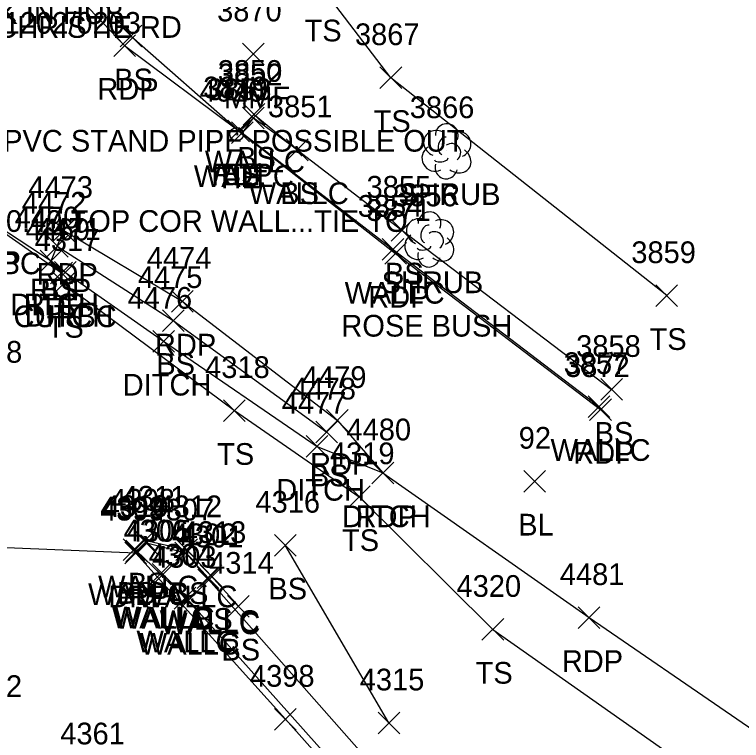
# Model space of a CAD drawing. Extents: x 1634209 to 1639641, y 608564 to 612258.
# Drawn here: x 1639319.3 to 1639386.3, y 611460.6 to 611527.5 of the extents above; entities that cross this region are included whole.
import ezdxf

# ---------------------------------------------------------------- set-up
doc = ezdxf.new("R2010")
doc.units = 0
for name, color, linetype in [('C_A', 7, 'Continuous'), ('C_C', 7, 'Continuous'), ('C_I', 7, 'Continuous'), ('C_TIC', 7, 'Continuous'), ('CBP', 7, 'Continuous'), ('D_A', 7, 'Continuous'), ('D_I', 7, 'Continuous'), ('D_TIC', 7, 'Continuous'), ('DD', 7, 'Continuous'), ('L_A', 7, 'Continuous'), ('L_C', 7, 'Continuous'), ('L_I', 7, 'Continuous'), ('L_TIC', 7, 'Continuous'), ('LELB', 7, 'Continuous'), ('LSH', 7, 'Continuous'), ('LW', 7, 'Continuous'), ('M_C', 7, 'Continuous'), ('P_A', 7, 'Continuous'), ('P_I', 7, 'Continuous'), ('P_TIC', 7, 'Continuous'), ('PET', 7, 'Continuous'), ('R_A', 7, 'Continuous'), ('R_I', 7, 'Continuous'), ('R_TIC', 7, 'Continuous'), ('RC', 7, 'Continuous'), ('RDP', 7, 'Continuous'), ('S_C', 7, 'Continuous')]:
    doc.layers.add(name, color=color, linetype=linetype)

msp = doc.modelspace()

# ---------------------------------------------------------------- linework, layer by layer
at = {"layer": 'C_TIC'}
for points in [[(1639366.207, 611483.502), (1639368.207, 611485.502)], [(1639368.207, 611483.502), (1639366.207, 611485.502)]]:
    msp.add_lwpolyline(points, dxfattribs=at)
at = {"layer": 'CBP'}
for radius in [0.625, 0.0833]:
    msp.add_circle((1639339.766, 611516.474), radius, dxfattribs=at)
at = {"layer": 'D_TIC'}
for points in [[(1639321.657, 611503.794), (1639323.657, 611505.794)], [(1639323.657, 611503.794), (1639321.657, 611505.794)], [(1639322.986, 611502.739), (1639324.986, 611504.739)], [(1639324.986, 611502.739), (1639322.986, 611504.739)], [(1639332.024, 611496.396), (1639334.024, 611498.396)], [(1639334.024, 611496.396), (1639332.024, 611498.396)], [(1639346.171, 611486.713), (1639348.171, 611488.713)], [(1639348.171, 611486.713), (1639346.171, 611488.713)], [(1639352.223, 611484.268), (1639354.223, 611486.268)], [(1639354.223, 611484.268), (1639352.223, 611486.268)]]:
    msp.add_lwpolyline(points, dxfattribs=at)
at = {"layer": 'DD'}
msp.add_lwpolyline([(1639322.657, 611504.794), (1639323.986, 611503.739), (1639333.024, 611497.396), (1639347.171, 611487.713), (1639353.223, 611485.268)], dxfattribs=at)
at = {"layer": 'L_TIC'}
for points in [[(1639329.033, 611524.513), (1639331.033, 611526.513)], [(1639331.033, 611524.513), (1639329.033, 611526.513)], [(1639340.304, 611522.866), (1639342.304, 611524.866)], [(1639342.304, 611522.866), (1639340.304, 611524.866)], [(1639352.963, 611520.678), (1639354.963, 611522.678)], [(1639354.963, 611520.678), (1639352.963, 611522.678)], [(1639340.362, 611517.296), (1639342.362, 611519.296)], [(1639342.362, 611517.296), (1639340.362, 611519.296)], [(1639340.292, 611516.968), (1639342.292, 611518.968)], [(1639342.292, 611516.968), (1639340.292, 611518.968)], [(1639338.944, 611515.771), (1639340.944, 611517.771)], [(1639340.944, 611515.771), (1639338.944, 611517.771)], [(1639339.276, 611515.609), (1639341.276, 611517.609)], [(1639341.276, 611515.609), (1639339.276, 611517.609)], [(1639344.333, 611514.034), (1639346.333, 611516.034)], [(1639346.333, 611514.034), (1639344.333, 611516.034)], [(1639344.333, 611514.034), (1639346.333, 611516.034)], [(1639346.333, 611514.034), (1639344.333, 611516.034)], [(1639353.985, 611506.628), (1639355.985, 611508.628)], [(1639355.985, 611506.628), (1639353.985, 611508.628)], [(1639322.225, 611505.158), (1639324.225, 611507.158)], [(1639324.225, 611505.158), (1639322.225, 611507.158)], [(1639353.17, 611504.865), (1639355.17, 611506.865)], [(1639355.17, 611504.865), (1639353.17, 611506.865)], [(1639322.847, 611501.725), (1639324.847, 611503.725)], [(1639324.847, 611501.725), (1639322.847, 611503.725)], [(1639378.384, 611500.598), (1639380.384, 611502.598)], [(1639380.384, 611500.598), (1639378.384, 611502.598)], [(1639332.914, 611498.304), (1639334.914, 611500.304)], [(1639334.914, 611498.304), (1639332.914, 611500.304)], [(1639373.294, 611491.958), (1639375.294, 611493.958)], [(1639375.294, 611491.958), (1639373.294, 611493.958)], [(1639372.143, 611490.379), (1639374.143, 611492.379)], [(1639374.143, 611490.379), (1639372.143, 611492.379)], [(1639338.548, 611490.013), (1639340.548, 611492.013)], [(1639340.548, 611490.013), (1639338.548, 611492.013)], [(1639347.053, 611488.031), (1639349.053, 611490.031)], [(1639349.053, 611488.031), (1639347.053, 611490.031)], [(1639350.056, 611482.073), (1639352.056, 611484.073)], [(1639352.056, 611482.073), (1639350.056, 611484.073)], [(1639330.299, 611478.069), (1639332.299, 611480.069)], [(1639332.299, 611478.069), (1639330.299, 611480.069)], [(1639330.455, 611477.798), (1639332.455, 611479.798)], [(1639332.455, 611477.798), (1639330.455, 611479.798)], [(1639343.241, 611477.608), (1639345.241, 611479.608)], [(1639345.241, 611477.608), (1639343.241, 611479.608)], [(1639329.289, 611477.208), (1639331.289, 611479.208)], [(1639331.289, 611477.208), (1639329.289, 611479.208)], [(1639329.539, 611477.086), (1639331.539, 611479.086)], [(1639331.539, 611477.086), (1639329.539, 611479.086)], [(1639329.539, 611477.086), (1639331.539, 611479.086)], [(1639331.539, 611477.086), (1639329.539, 611479.086)], [(1639334.156, 611477.192), (1639336.156, 611479.192)], [(1639336.156, 611477.192), (1639334.156, 611479.192)], [(1639334.074, 611476.887), (1639336.074, 611478.887)], [(1639336.074, 611476.887), (1639334.074, 611478.887)], [(1639331.73, 611474.958), (1639333.73, 611476.958)], [(1639333.73, 611474.958), (1639331.73, 611476.958)], [(1639331.968, 611474.929), (1639333.968, 611476.929)], [(1639333.968, 611474.929), (1639331.968, 611476.929)], [(1639336.126, 611474.615), (1639338.126, 611476.615)], [(1639338.126, 611474.615), (1639336.126, 611476.615)], [(1639336.188, 611474.408), (1639338.188, 611476.408)], [(1639338.188, 611474.408), (1639336.188, 611476.408)], [(1639336.387, 611474.815), (1639338.387, 611476.815)], [(1639338.387, 611474.815), (1639336.387, 611476.815)], [(1639333.995, 611472.73), (1639335.995, 611474.73)], [(1639335.995, 611472.73), (1639333.995, 611474.73)], [(1639334.302, 611472.537), (1639336.302, 611474.537)], [(1639336.302, 611472.537), (1639334.302, 611474.537)], [(1639338.915, 611471.986), (1639340.915, 611473.986)], [(1639340.915, 611471.986), (1639338.915, 611473.986)], [(1639362.36, 611469.852), (1639364.36, 611471.852)], [(1639364.36, 611469.852), (1639362.36, 611471.852)], [(1639352.791, 611461.233), (1639354.791, 611463.233)], [(1639354.791, 611461.233), (1639352.791, 611463.233)]]:
    msp.add_lwpolyline(points, dxfattribs=at)
at = {"layer": 'LELB'}
for points in [[(1639319.732, 611545.773), (1639322.72, 611534.263), (1639330.033, 611525.513), (1639339.944, 611516.771), (1639341.362, 611518.296), (1639345.333, 611515.034), (1639354.985, 611507.628), (1639374.294, 611492.958)], [(1639379.384, 611501.598), (1639353.963, 611521.678), (1639347.601, 611530.023), (1639334.248, 611539.828)], [(1639323.225, 611506.158), (1639333.914, 611499.304), (1639348.053, 611489.031)], [(1639323.847, 611502.725), (1639339.548, 611491.013), (1639351.056, 611483.073), (1639363.36, 611470.852), (1639390.679, 611451.611), (1639402.909, 611427.46), (1639391.145, 611410.38), (1639370.449, 611391.907), (1639349.836, 611374.39), (1639349.875, 611367.832), (1639363.625, 611352.92)], [(1639330.289, 611478.208), (1639331.299, 611479.069), (1639335.156, 611478.192), (1639337.387, 611475.815), (1639339.915, 611472.986)], [(1639353.791, 611462.233), (1639344.241, 611478.608)]]:
    msp.add_lwpolyline(points, dxfattribs=at)
at = {"layer": 'LSH'}
for p, q in [((1639359.069, 611514.952), (1639359.069, 611514.952)), ((1639359.069, 611514.952), (1639359.069, 611514.952)), ((1639357.483, 611506.828), (1639357.483, 611506.828)), ((1639357.483, 611506.828), (1639357.483, 611506.828))]:
    msp.add_line(p, q, dxfattribs=at)
for centre in [(1639359.116, 611516.385), (1639357.529, 611508.262)]:
    msp.add_arc(centre, 1.047, 335.52715, 180.95627, dxfattribs=at)
for centre, major_axis, ratio, start_param, end_param in [((1639358.278, 611515.618), (1.21, -0.512), 0.895232, 1.570796, 4.712389), ((1639360.111, 611515.535), (-1.141, -0.483), 0.949671, 1.570796, 4.712389), ((1639358.861, 611515.41), (-0.208, -0.792), 0.645439, 3.141593, 6.283185), ((1639357.986, 611514.243), (0.584, -1.042), 0.959034, 3.141593, 6.283185), ((1639359.569, 611514.785), (-0.5, 0.667), 0.989748, 3.141593, 6.283185), ((1639360.07, 611514.118), (-1.09, 0.792), 0.841452, 1.570796, 4.712389), ((1639358.611, 611514.201), (-0.625, -0.083), 0.423636, 0, 3.141593), ((1639359.07, 611513.452), (0.265, 1.061), 0.942809, 1.570796, 4.712389), ((1639356.691, 611507.495), (1.21, -0.512), 0.895232, 1.570796, 4.712389), ((1639358.524, 611507.412), (-1.141, -0.483), 0.949671, 1.570796, 4.712389), ((1639357.274, 611507.287), (-0.208, -0.792), 0.645439, 3.141593, 6.283185), ((1639356.399, 611506.12), (0.584, -1.042), 0.959034, 3.141593, 6.283185), ((1639357.983, 611506.662), (-0.5, 0.667), 0.989748, 3.141593, 6.283185), ((1639358.483, 611505.995), (-1.09, 0.792), 0.841452, 1.570796, 4.712389), ((1639357.024, 611506.078), (-0.625, -0.083), 0.423636, 0, 3.141593), ((1639357.483, 611505.328), (0.265, 1.061), 0.942809, 1.570796, 4.712389)]:
    msp.add_ellipse(centre, major_axis=major_axis, ratio=ratio, start_param=start_param, end_param=end_param, dxfattribs=at)
at = {"layer": 'LW'}
for points in [[(1639345.333, 611515.034), (1639341.292, 611517.968), (1639340.276, 611516.609), (1639354.17, 611505.865), (1639373.143, 611491.379)], [(1639350.672, 611344.201), (1639330.699, 611370.33), (1639326.662, 611374.868), (1639351.89, 611402.586), (1639353.191, 611402.191), (1639371.825, 611423.866), (1639369.52, 611438.787), (1639337.188, 611475.408), (1639337.126, 611475.615), (1639335.074, 611477.887), (1639331.455, 611478.798), (1639330.539, 611478.086)], [(1639347.959, 611343.04), (1639328.333, 611368.981), (1639322.617, 611374.773), (1639350.079, 611404.446), (1639350.847, 611404.494), (1639369.725, 611425.901), (1639367.306, 611437.612), (1639335.302, 611473.537), (1639334.995, 611473.73), (1639332.968, 611475.929), (1639332.73, 611475.958), (1639330.539, 611478.086)]]:
    msp.add_lwpolyline(points, dxfattribs=at)
at = {"layer": 'P_TIC'}
for points in [[(1639328.438, 611523.641), (1639330.438, 611525.641)], [(1639330.438, 611523.641), (1639328.438, 611525.641)], [(1639338.944, 611515.771), (1639340.944, 611517.771)], [(1639340.944, 611515.771), (1639338.944, 611517.771)], [(1639322.83, 611506.6), (1639324.83, 611508.6)], [(1639324.83, 611506.6), (1639322.83, 611508.6)], [(1639322.225, 611505.158), (1639324.225, 611507.158)], [(1639324.225, 611505.158), (1639322.225, 611507.158)], [(1639353.394, 611504.486), (1639355.394, 611506.486)], [(1639355.394, 611504.486), (1639353.394, 611506.486)], [(1639321.657, 611503.794), (1639323.657, 611505.794)], [(1639323.657, 611503.794), (1639321.657, 611505.794)], [(1639333.74, 611500.085), (1639335.74, 611502.085)], [(1639335.74, 611500.085), (1639333.74, 611502.085)], [(1639372.276, 611490.106), (1639374.276, 611492.106)], [(1639374.276, 611490.106), (1639372.276, 611492.106)], [(1639348.037, 611489.097), (1639350.037, 611491.097)], [(1639350.037, 611489.097), (1639348.037, 611491.097)], [(1639352.223, 611484.268), (1639354.223, 611486.268)], [(1639354.223, 611484.268), (1639352.223, 611486.268)], [(1639371.223, 611470.939), (1639373.223, 611472.939)], [(1639373.223, 611470.939), (1639371.223, 611472.939)]]:
    msp.add_lwpolyline(points, dxfattribs=at)
at = {"layer": 'PET'}
for points in [[(1639314.656, 611547.033), (1639316.63, 611540.173), (1639320.993, 611533.529), (1639329.438, 611524.641), (1639339.944, 611516.771), (1639354.394, 611505.486), (1639373.276, 611491.106)], [(1639267.876, 611454.496), (1639285.596, 611485.313), (1639298.768, 611508.597), (1639301.735, 611510.388), (1639304.907, 611511.217), (1639309.937, 611511.307), (1639314.005, 611510.179), (1639316.743, 611508.691), (1639322.657, 611504.794), (1639323.225, 611506.158), (1639323.83, 611507.6), (1639334.74, 611501.085), (1639349.037, 611490.097), (1639353.223, 611485.268), (1639372.223, 611471.939), (1639399.454, 611453.276)]]:
    msp.add_lwpolyline(points, dxfattribs=at)
at = {"layer": 'R_TIC'}
for points in [[(1639322.62, 611502.693), (1639324.62, 611504.693)], [(1639324.62, 611502.693), (1639322.62, 611504.693)], [(1639329.454, 611476.882), (1639331.454, 611478.882)], [(1639331.454, 611476.882), (1639329.454, 611478.882)], [(1639343.247, 611461.57), (1639345.247, 611463.57)], [(1639345.247, 611461.57), (1639343.247, 611463.57)]]:
    msp.add_lwpolyline(points, dxfattribs=at)
at = {"layer": 'RC'}
msp.add_lwpolyline([(1639305.25, 611502.148), (1639304.277, 611500.747), (1639292.233, 611481.833), (1639291.134, 611480.575), (1639289.383, 611479.947), (1639287.929, 611480.279), (1639286.687, 611481.225), (1639285.788, 611482.527), (1639285.487, 611483.753), (1639285.827, 611485.239), (1639298.852, 611508.417), (1639301.855, 611510.301), (1639304.868, 611511.156), (1639309.979, 611511.225), (1639313.824, 611510.093), (1639316.634, 611508.571), (1639323.62, 611503.693)], dxfattribs=at)
at = {"layer": 'RDP'}
msp.add_lwpolyline([(1639344.001, 611398.538), (1639368.892, 611426.032), (1639366.487, 611437.613), (1639344.247, 611462.57), (1639330.454, 611477.882), (1639311.81, 611478.629), (1639290.862, 611480.062), (1639289.304, 611479.764), (1639287.86, 611480.101), (1639286.517, 611481.064), (1639285.661, 611482.423), (1639285.361, 611483.798), (1639285.596, 611485.313)], dxfattribs=at)

# ---------------------------------------------------------------- texts
at = {"layer": 'C_A'}
for s, p in [('TIE', (1639337.845, 611511.474)), ('BL', (1639365.695, 611479.502))]:
    msp.add_text(s, height=2, dxfattribs=at).set_placement(p)
at = {"layer": 'C_C'}
for s, p in [('TACK IN HUB', (1639312.458, 611526.62)), ('70.49 TOP COR WALL...TIE TO', (1639317.018, 611507.474))]:
    msp.add_text(s, height=2, dxfattribs=at).set_placement(p)
at = {"layer": 'C_I'}
for s, p in [('4020', (1639336.341, 611519.474)), ('92', (1639365.742, 611487.502))]:
    msp.add_text(s, height=2, dxfattribs=at).set_placement(p)
at = {"layer": 'D_A'}
for p in [(1639318.893, 611499.794), (1639320.222, 611498.739), (1639329.26, 611492.396), (1639343.407, 611482.713), (1639349.459, 611480.268)]:
    msp.add_text('DITCH', height=2, dxfattribs=at).set_placement(p)
at = {"layer": 'D_I'}
for s, p in [('4470', (1639319.31, 611507.794)), ('4471', (1639321.293, 611506.739)), ('4476', (1639329.709, 611500.396)), ('4477', (1639343.911, 611490.713)), ('4480', (1639349.876, 611488.268))]:
    msp.add_text(s, height=2, dxfattribs=at).set_placement(p)
at = {"layer": 'L_A'}
for s, p in [('TS', (1639346.01, 611525.023)), ('BS', (1639328.474, 611520.513)), ('MMF', (1639338.588, 611518.866)), ('TS', (1639352.373, 611516.678)), ('BS', (1639339.803, 611513.296)), ('WALLC', (1639336.828, 611512.968)), ('BS', (1639338.385, 611511.771)), ('WALLC', (1639335.812, 611511.609)), ('WALLC', (1639340.869, 611510.034)), ('BS', (1639343.774, 611510.034)), ('SHRUB', (1639354.699, 611509.952)), ('BS', (1639353.426, 611502.628)), ('SHRUB', (1639353.113, 611501.828)), ('BS', (1639321.666, 611501.158)), ('WALLC', (1639349.706, 611500.865)), ('TS', (1639322.256, 611497.725)), ('TS', (1639377.793, 611496.598)), ('BS', (1639332.355, 611494.304)), ('BS', (1639372.735, 611487.958)), ('WALLC', (1639368.678, 611486.379)), ('TS', (1639337.957, 611486.013)), ('BS', (1639346.494, 611484.031)), ('TS', (1639349.465, 611478.073)), ('WALLC', (1639326.991, 611473.798)), ('BS', (1639329.74, 611474.069)), ('BS', (1639342.682, 611473.608)), ('WALLC', (1639326.075, 611473.086)), ('WALLC', (1639326.075, 611473.086)), ('BS', (1639328.73, 611473.208)), ('WALLC', (1639330.61, 611472.887)), ('BS', (1639333.597, 611473.192)), ('WALLC', (1639328.265, 611470.958)), ('WALLC', (1639328.504, 611470.929)), ('WALLC', (1639332.662, 611470.615)), ('WALLC', (1639332.724, 611470.408)), ('BS', (1639335.828, 611470.815)), ('WALLC', (1639330.53, 611468.73)), ('WALLC', (1639330.837, 611468.537)), ('BS', (1639338.356, 611467.986)), ('TS', (1639361.769, 611465.852))]:
    msp.add_text(s, height=2, dxfattribs=at).set_placement(p)
at = {"layer": 'L_C'}
for s, p in [('50 PVC STAND PIPE POSSIBLE OUT', (1639314.525, 611514.866)), ('ROSE BUSH', (1639349.404, 611497.828))]:
    msp.add_text(s, height=2, dxfattribs=at).set_placement(p)
at = {"layer": 'L_I'}
for s, p in [('3870', (1639337.958, 611526.866)), ('3867', (1639350.656, 611524.678)), ('3850', (1639338.015, 611521.296)), ('3852', (1639338.032, 611520.968)), ('3849', (1639336.677, 611519.771)), ('3853', (1639337.017, 611519.609)), ('3851', (1639342.64, 611518.034)), ('3851', (1639342.64, 611518.034)), ('3866', (1639355.707, 611517.952)), ('3855', (1639351.725, 611510.628)), ('3856', (1639354.168, 611509.828)), ('4472', (1639319.965, 611509.158)), ('3854', (1639350.91, 611508.865)), ('4317', (1639321.154, 611505.725)), ('3859', (1639376.116, 611504.598)), ('4475', (1639330.654, 611502.304)), ('3858', (1639371.034, 611495.958)), ('3857', (1639369.883, 611494.379)), ('4318', (1639336.855, 611494.013)), ('4478', (1639344.794, 611492.031)), ('4319', (1639348.355, 611486.073)), ('4308', (1639328.117, 611481.798)), ('4311', (1639329.173, 611482.069)), ('4316', (1639341.493, 611481.608)), ('4309', (1639327.193, 611481.086)), ('4309', (1639327.193, 611481.086)), ('4310', (1639327.51, 611481.208)), ('4312', (1639332.463, 611481.192)), ('4307', (1639331.736, 611480.887)), ('4306', (1639329.336, 611478.958)), ('4305', (1639329.63, 611478.929)), ('4302', (1639333.788, 611478.615)), ('4301', (1639334.417, 611478.408)), ('4313', (1639334.694, 611478.815)), ('4304', (1639331.656, 611476.73)), ('4303', (1639331.963, 611476.537)), ('4314', (1639337.223, 611475.986)), ('4320', (1639360.013, 611473.852)), ('4315', (1639351.098, 611465.233)), ('4362', (1639314.04, 611464.628)), ('4361', (1639323.508, 611460.263))]:
    msp.add_text(s, height=2, dxfattribs=at).set_placement(p)
at = {"layer": 'M_C'}
msp.add_text('WITH CAP D + A R BELL LS638', height=2, dxfattribs=at).set_placement((1639280.988, 611495.423))
at = {"layer": 'P_A'}
for p in [(1639326.926, 611519.641), (1639337.432, 611511.771), (1639314.231, 611503.691), (1639321.318, 611502.6), (1639320.713, 611501.158), (1639351.882, 611500.486), (1639320.145, 611499.794), (1639332.229, 611496.085), (1639370.764, 611486.106), (1639346.525, 611485.097), (1639350.711, 611480.268), (1639369.711, 611466.939)]:
    msp.add_text('RDP', height=2, dxfattribs=at).set_placement(p)
at = {"layer": 'P_I'}
for s, p in [('3849', (1639336.677, 611519.771)), ('4473', (1639320.57, 611510.6)), ('4472', (1639319.965, 611509.158)), ('3871', (1639351.701, 611508.486)), ('4470', (1639319.31, 611507.794)), ('4474', (1639331.481, 611504.085)), ('3872', (1639370.017, 611494.106)), ('4479', (1639345.769, 611493.097)), ('4480', (1639349.876, 611488.268)), ('4481', (1639369.53, 611474.939))]:
    msp.add_text(s, height=2, dxfattribs=at).set_placement(p)
at = {"layer": 'R_A'}
for s, p in [('CURBC', (1639312.217, 611503.571)), ('CURBC', (1639319.203, 611498.693)), ('DRP', (1639327.942, 611472.882))]:
    msp.add_text(s, height=2, dxfattribs=at).set_placement(p)
at = {"layer": 'R_I'}
for s, p in [('4469', (1639320.305, 611506.693)), ('4399', (1639327.187, 611480.882)), ('4398', (1639340.988, 611465.57))]:
    msp.add_text(s, height=2, dxfattribs=at).set_placement(p)
at = {"layer": 'S_C'}
for s, p in [('0140/1202/0203', (1639311.606, 611525.726)), ('STOP   CHRISTIE RD', (1639308.107, 611525.35))]:
    msp.add_text(s, height=2, dxfattribs=at).set_placement(p)

doc.saveas('drawing.dxf')
